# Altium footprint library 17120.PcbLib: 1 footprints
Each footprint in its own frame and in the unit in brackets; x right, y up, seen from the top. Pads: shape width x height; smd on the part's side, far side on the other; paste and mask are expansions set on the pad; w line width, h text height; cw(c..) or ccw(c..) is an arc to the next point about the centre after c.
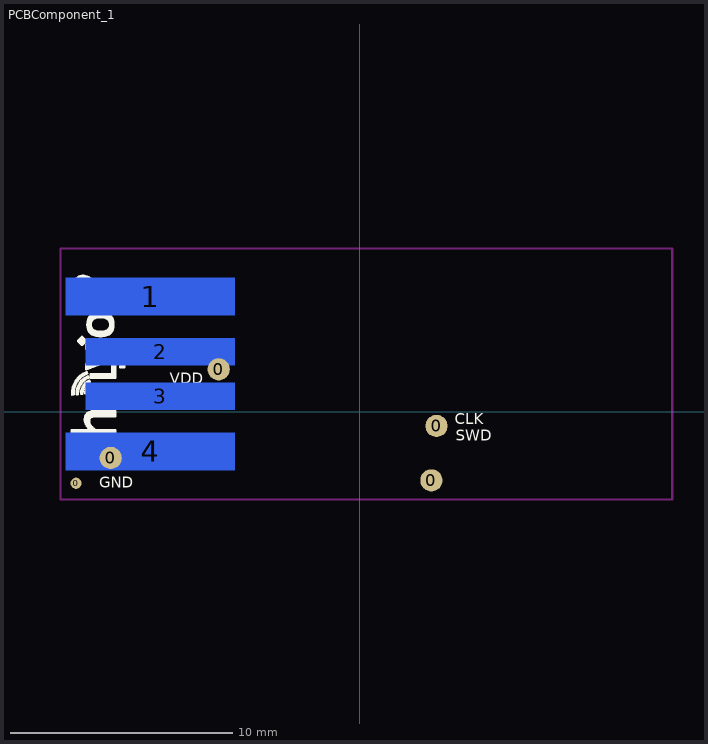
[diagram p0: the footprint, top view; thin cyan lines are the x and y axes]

## PCBComponent_1 [mm]
pads (9):
  round 0.5 smd: 0(-12.784,-3.221)
  round 1 smd: 0(-11.224,-2.081) 0(-6.364,1.909) 0(3.216,-3.091) 0(3.446,-0.641)
  rect 7.6x1.7 smd far side: 1(-9.444,5.189) 4(-9.444,-1.791)
  rect 6.7x1.2 smd far side: 2(-8.994,2.699) 3(-8.994,0.699)
Top Overlay:
  circle w0.15: c-12.456,5.65 r0.45
  region: -11.056,4.79 -11.056,5.07 -11.216,5.07 -11.216,4.79
  region: -12.026,4.49 -12.026,5.06 -12.126,5.06 -12.126,4.49
  region: -11.086,4.67 -11.086,4.81 -12.426,4.81 -12.426,4.67
  region: -11.347,4.381 -11.46,4.268 -11.269,4.077 -11.156,4.19
  region: -11.182,3.628 -11.295,3.741 -11.486,3.55 -11.373,3.437
  region: -11.933,4.247 -12.046,4.36 -12.237,4.169 -12.124,4.056
  region: -12.093,3.763 -12.206,3.65 -12.015,3.459 -11.902,3.572
  region: -11.306,3.43 -11.306,3.62 -11.976,3.62 -11.976,3.43
  region: -11.136,3.57 -11.136,4.21 -11.296,4.21 -11.296,3.57
  region: -11.296,4.25 -11.296,4.42 -12.046,4.42 -12.046,4.25
  region: -12.116,3.62 -12.116,4.27 -12.246,4.27 -12.246,3.62
  region: -12.35,3.164 -12.506,3.32 -12.654,3.172 -12.499,3.016
  region: -11.186,3.15 -11.186,3.23 -12.216,3.23 -12.216,3.15
  region: -10.646,2.03 -10.646,2.39 -10.796,2.39 -10.796,2.03
  region: -12.272,3.005 -12.337,2.826 -10.789,2.263 -10.724,2.442
  region: -12.346,2.112 -12.276,1.92 -10.984,2.39 -11.054,2.582
  region: -11.066,1.66 -11.066,2.15 -11.136,2.15 -11.136,1.66
  region: -11.066,1.57 -11.066,1.66 -12.096,1.66 -12.096,1.57
  region: -11.106,0.91 -11.106,1.03 -11.216,1.03 -11.216,0.91
  region: -11.106,0.24 -11.106,0.35 -11.226,0.35 -11.226,0.24
  region: -11.986,0.9 -11.986,1.06 -12.106,1.06 -12.106,0.9
  region: -11.966,0.24 -11.966,0.35 -12.136,0.35 -12.136,0.24
  region: -11.126,0.99 -11.126,1.07 -12.016,1.07 -12.016,0.99
  region: -12.066,0.33 -12.066,0.99 -12.146,0.99 -12.146,0.33
  region: -11.046,0.26 -11.046,1.01 -11.136,1.01 -11.136,0.26
  region: -11.086,0.18 -11.086,0.26 -12.116,0.26 -12.116,0.18
  region: -12.145,0.028 -12.41,-0.288 -12.221,-0.446 -11.956,-0.13
  region: -11.066,-0.16 -11.066,-0.01 -12.246,-0.01 -12.246,-0.16
  region: -11.916,-0.9 -12.291,-0.25 -12.438,-0.335 -12.063,-0.985
  region: -11.066,-1.03 -11.066,-0.87 -12.946,-0.87 -12.946,-1.03
  lines w0.1: -12.703,3.188 -12.518,3.373 -12.333,3.188 -12.518,3.003 -12.703,3.188 ; -12.016,3.458 ccw(c-11.687,4.256) -11.356,3.459 ccw(c-11.51,3.828) -11.129,3.706 ccw(c-11.812,3.926) -11.129,4.145 ccw(c-11.51,4.023) -11.357,4.392 ccw(c-11.687,3.596) -12.016,4.393 ccw(c-11.864,4.023) -12.244,4.146 ccw(c-11.562,3.926) -12.245,3.706 ccw(c-11.864,3.828) -12.017,3.459 ; -11.944,3.643 ccw(c-11.688,4.365) -11.428,3.645 ccw(c-11.516,3.889) -11.289,3.763 ccw(c-11.582,3.926) -11.289,4.088 ccw(c-11.516,3.962) -11.428,4.207 ccw(c-11.688,3.486) -11.943,4.208 ccw(c-11.857,3.963) -12.082,4.094 ccw(c-11.792,3.926) -12.082,3.758 ccw(c-11.857,3.888) -11.943,3.643 ; -10.807,2 -10.613,2.006 ccw(c-11.184,2.138) -10.601,2.201 ccw(c-10.864,2.173) -10.69,2.371 ccw(c-11.169,1.825) -10.918,2.507 -12.332,3.027 -12.332,2.82 -11.34,2.488 -11.34,2.464 -12.326,2.134 -12.326,1.911 -11.072,2.378 -10.934,2.331 cw(c-11.005,2.123) -10.787,2.1 cw(c-11.332,2.158) -10.807,2 ; -12.99,-1.071 -12.99,-0.823 -12.135,-0.823 cw(c-11.618,-0.171) -12.366,-0.536 cw(c-11.868,-0.356) -12.389,-0.26 cw(c-12.054,-0.322) -12.082,0.017 cw(c-11.862,-2.71) -11.862,0.026 -11.022,0.026 -11.022,-0.202 -11.862,-0.202 ccw(c-11.862,-1.037) -12.059,-0.226 ccw(c-12.016,-0.401) -12.196,-0.403 ccw(c-11.801,-0.398) -12.134,-0.611 ccw(c-11.434,-0.114) -11.919,-0.823 -11.022,-0.823 -11.022,-1.071 -12.99,-1.071 ; -12.965,0.763 cw(c-11.927,0.826) -12.309,1.793 -12.286,1.723 ccw(c-11.927,0.826) -12.892,0.771 -12.965,0.764 ; -12.766,0.784 cw(c-11.927,0.826) -12.247,1.603 -12.224,1.532 ccw(c-11.927,0.826) -12.692,0.791 -12.766,0.784 ; -12.567,0.804 cw(c-11.927,0.826) -12.185,1.412 -12.162,1.341 ccw(c-11.927,0.826) -12.493,0.812 -12.567,0.804 ; -12.47,4.824 -12.143,4.824 -12.143,5.095 -11.994,5.095 -11.994,4.818 -11.385,4.818 ccw(c-11.388,5.218) -11.262,4.839 ccw(c-11.294,4.934) -11.203,4.891 ccw(c-11.409,4.989) -11.181,4.999 ccw(c-11.281,4.994) -11.205,5.059 ccw(c-11.342,4.942) -11.247,5.095 -11.049,5.095 cw(c-11.448,4.949) -11.044,4.814 ccw(c-10.722,4.707) -11.05,4.796 cw(c-11.243,4.848) -11.184,4.657 cw(c-11.272,4.942) -11.267,4.644 -11.994,4.632 -11.994,4.458 -12.143,4.458 -12.143,4.632 -12.398,4.632 -12.47,4.824 ; -12.387,0.823 cw(c-11.927,0.826) -12.129,1.239 -12.106,1.168 ccw(c-11.927,0.826) -12.313,0.83 -12.387,0.823 ; -12.256,3.105 -12.256,3.268 -11.146,3.268 -11.146,3.105 -12.256,3.105 ; -12.191,0.429 ccw(c-11.911,0.429) -11.911,0.149 -11.281,0.149 ccw(c-11.281,0.429) -11.001,0.429 -11.001,0.817 ccw(c-11.281,0.817) -11.281,1.097 -11.911,1.097 ccw(c-11.911,0.817) -12.191,0.817 -12.191,0.429 ; -12.141,1.527 -12.141,1.693 -11.169,1.693 -11.169,2.188 -11.023,2.188 -11.023,1.527 -12.141,1.527 ; -12.059,0.491 ccw(c-11.839,0.491) -11.839,0.271 -11.354,0.271 ccw(c-11.354,0.491) -11.134,0.491 -11.134,0.765 ccw(c-11.354,0.765) -11.354,0.985 -11.839,0.985 ccw(c-11.839,0.765) -12.059,0.765 -12.059,0.491
  text "R" at -12.206,5.5 h0.5
  text "VDD" at -8.574,1.259 h0.5
  text "GND" at -11.744,-3.431 h0.5
  text "CLK" at 4.276,-0.571 h0.5
  text "SWD" at 4.306,-1.311 h0.5
Bottom Overlay:
  rectangle: -12.434,-0.941 -5.544,0.099
  rectangle: -12.544,1.349 -5.534,2.049
  rectangle: -13.424,-0.941 -12.414,3.499
  rectangle: -13.424,3.319 -5.534,4.339
  lines w0.152: -13.491,-2.821 -13.491,6.219 -5.464,6.219 -5.464,-2.821 -13.491,-2.821
  text "HOLYIOT-17120-NRF52840" at 8.046,-3.491 h0.7
Keep-Out Layer:
  lines w0.1: -13.491,-3.953 14.059,-3.953 14.059,7.347 -13.491,7.347 -13.491,-3.953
